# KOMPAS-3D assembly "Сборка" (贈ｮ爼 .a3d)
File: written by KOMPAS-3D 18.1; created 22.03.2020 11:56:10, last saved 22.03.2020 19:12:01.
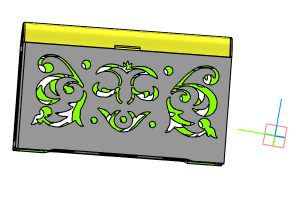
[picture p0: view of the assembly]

Document properties: Автор: windwican@hotmail.com; Полное имя файла: C:\Users\windw\Desktop\shkatilka1\bez petli\Измененная\Сборка.a3d

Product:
- Part/product: Сборка
    Масса: 20.4567
  - Component [detail]: Основание  | Масса: 4.38205; source file: Dno.m3d
  - Component [detail]: Стенка  | Масса: 5.17309; source file: Stenka.m3d
  - Component [detail]: bok1  | qty 2  | Масса: 2.45203; source file: Bokovina.m3d
  - Component [detail]: Крышка  | Материал: Полиамид П-12Б-20  ТУ 6-05-898-73 (density 1020 kg/m3); Масса: 0.583422; source file: крышка.m3d
  - Component [detail]: Стенка с петлёй  | Масса: 5.41403; source file: Stenka s petlei.m3d

Referenced files in C:\Users\windw\Desktop\shkatilka1\bez petli\Измененная\: Bokovina.m3d, Stenka.m3d, Dno.m3d, крышка.m3d, Stenka s petlei.m3d
Referenced files in C:\Users\windw\Desktop\shkatilka1\bez petli\: Bokovina.m3d, Stenka.m3d
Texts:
  Точка начала. Х
  Точка начала. Y
  Точка начала. Z
  bok1 (1)
  bok1 (2)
